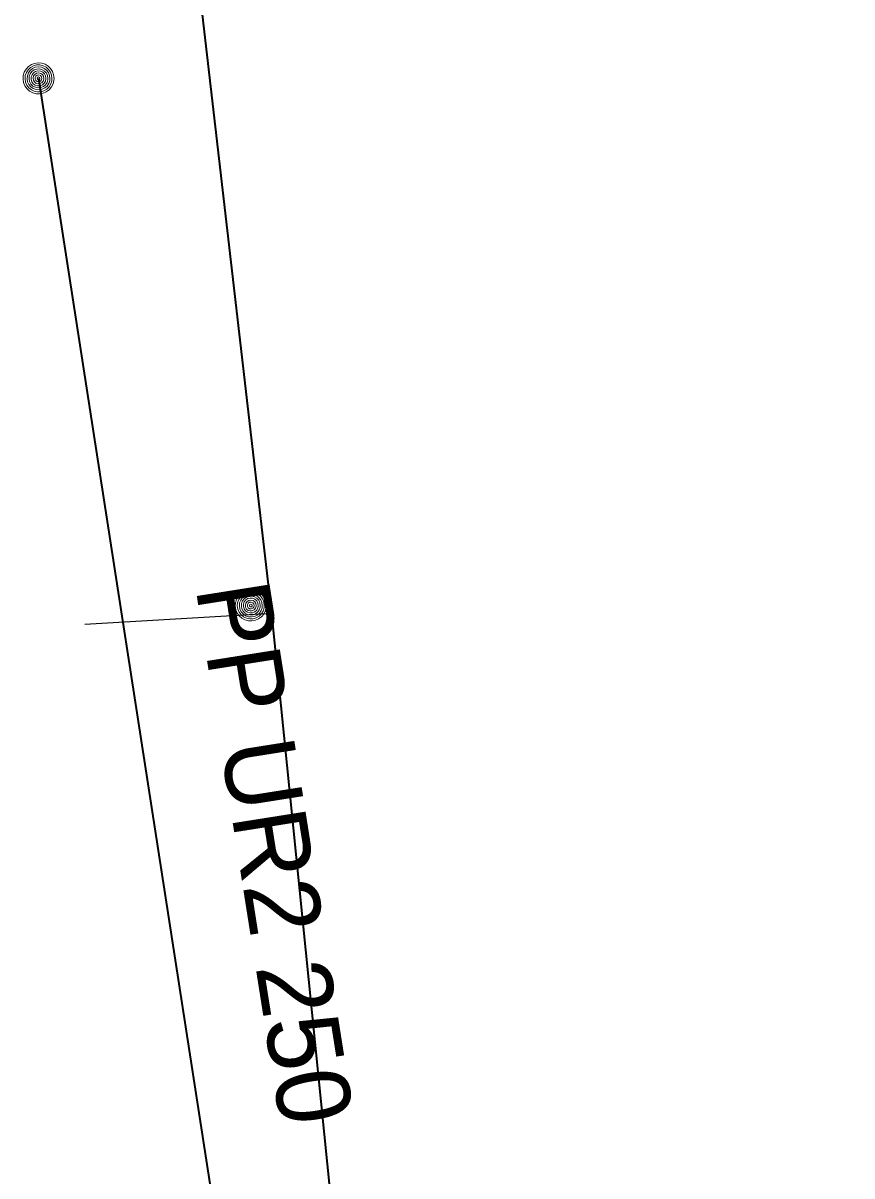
# Model space of a CAD drawing. Extents: x -866761 to -866592, y -1013996 to -1013877.
# Drawn here: x -866633.41 to -866621.04, y -1013918.84 to -1013901.63 of the extents above; entities that cross this region are included whole.
import ezdxf

# ---------------------------------------------------------------- set-up
doc = ezdxf.new("R2010")
doc.units = 0
doc.header["$LTSCALE"] = 0.44
for name, color, linetype, lineweight in [('1', 7, 'Continuous', 35), ('12', 7, 'Continuous', 13), ('21', 7, 'Continuous', 35), ('3', 7, 'Continuous', 25), ('32', 7, 'Continuous', 13)]:
    doc.layers.add(name, color=color, linetype=linetype, lineweight=lineweight)

msp = doc.modelspace()

# ---------------------------------------------------------------- linework, layer by layer
at = {"layer": '1'}
msp.add_lwpolyline([(-866621.036, -1013976.325), (-866622.91, -1013968.373), (-866626.376, -1013941.619), (-866627.386, -1013933.289), (-866629.697, -1013910.45), (-866632.18, -1013888.99), (-866632.46, -1013887.48), (-866632.668, -1013884.429)], dxfattribs=at)
at = {"layer": '12'}
for points in [[(-866629.78, -1013910.329), (-866629.786, -1013910.277), (-866629.803, -1013910.227), (-866629.832, -1013910.183), (-866629.869, -1013910.146), (-866629.914, -1013910.119), (-866629.964, -1013910.102), (-866630.017, -1013910.098), (-866630.069, -1013910.105), (-866630.118, -1013910.124), (-866630.161, -1013910.153), (-866630.197, -1013910.192), (-866630.223, -1013910.237), (-866630.239, -1013910.288), (-866630.242, -1013910.34), (-866630.234, -1013910.392), (-866630.214, -1013910.441), (-866630.183, -1013910.484), (-866630.144, -1013910.518), (-866630.098, -1013910.544), (-866630.047, -1013910.558), (-866629.994, -1013910.56), (-866629.943, -1013910.55), (-866629.895, -1013910.529), (-866629.852, -1013910.498), (-866629.818, -1013910.457), (-866629.794, -1013910.411), (-866629.782, -1013910.36)], [(-866629.81, -1013910.329), (-866629.816, -1013910.28), (-866629.833, -1013910.234), (-866629.861, -1013910.194), (-866629.898, -1013910.162), (-866629.942, -1013910.14), (-866629.99, -1013910.129), (-866630.039, -1013910.129), (-866630.086, -1013910.142), (-866630.129, -1013910.166), (-866630.165, -1013910.199), (-866630.192, -1013910.24), (-866630.208, -1013910.287), (-866630.212, -1013910.336), (-866630.205, -1013910.384), (-866630.186, -1013910.429), (-866630.156, -1013910.469), (-866630.118, -1013910.5), (-866630.074, -1013910.52), (-866630.026, -1013910.53), (-866629.977, -1013910.528), (-866629.93, -1013910.513), (-866629.887, -1013910.488), (-866629.853, -1013910.454), (-866629.827, -1013910.412), (-866629.813, -1013910.365)], [(-866629.84, -1013910.329), (-866629.846, -1013910.284), (-866629.863, -1013910.242), (-866629.891, -1013910.207), (-866629.927, -1013910.18), (-866629.969, -1013910.163), (-866630.014, -1013910.158), (-866630.059, -1013910.164), (-866630.1, -1013910.183), (-866630.135, -1013910.211), (-866630.162, -1013910.248), (-866630.178, -1013910.29), (-866630.182, -1013910.335), (-866630.175, -1013910.38), (-866630.156, -1013910.421), (-866630.127, -1013910.455), (-866630.09, -1013910.481), (-866630.047, -1013910.497), (-866630.002, -1013910.5), (-866629.957, -1013910.492), (-866629.917, -1013910.472), (-866629.883, -1013910.443), (-866629.857, -1013910.405), (-866629.843, -1013910.362)], [(-866629.87, -1013910.329), (-866629.875, -1013910.288), (-866629.893, -1013910.251), (-866629.92, -1013910.22), (-866629.955, -1013910.199), (-866629.995, -1013910.188), (-866630.036, -1013910.19), (-866630.075, -1013910.203), (-866630.109, -1013910.227), (-866630.134, -1013910.259), (-866630.149, -1013910.297), (-866630.152, -1013910.338), (-866630.144, -1013910.378), (-866630.124, -1013910.414), (-866630.095, -1013910.443), (-866630.058, -1013910.462), (-866630.018, -1013910.47), (-866629.977, -1013910.466), (-866629.939, -1013910.451), (-866629.907, -1013910.425), (-866629.884, -1013910.391), (-866629.871, -1013910.352)], [(-866629.9, -1013910.329), (-866629.905, -1013910.293), (-866629.923, -1013910.261), (-866629.949, -1013910.236), (-866629.983, -1013910.221), (-866630.019, -1013910.218), (-866630.054, -1013910.226), (-866630.085, -1013910.246), (-866630.108, -1013910.274), (-866630.121, -1013910.308), (-866630.121, -1013910.345), (-866630.11, -1013910.38), (-866630.089, -1013910.409), (-866630.059, -1013910.43), (-866630.024, -1013910.44), (-866629.987, -1013910.438), (-866629.953, -1013910.424), (-866629.926, -1013910.401), (-866629.907, -1013910.369), (-866629.9, -1013910.334)], [(-866629.93, -1013910.329), (-866629.935, -1013910.298), (-866629.952, -1013910.272), (-866629.978, -1013910.255), (-866630.008, -1013910.248), (-866630.039, -1013910.252), (-866630.066, -1013910.269), (-866630.084, -1013910.293), (-866630.092, -1013910.324), (-866630.088, -1013910.354), (-866630.073, -1013910.382), (-866630.049, -1013910.401), (-866630.019, -1013910.41), (-866629.988, -1013910.407), (-866629.96, -1013910.393), (-866629.94, -1013910.369), (-866629.93, -1013910.34)], [(-866629.96, -1013910.329), (-866629.965, -1013910.305), (-866629.982, -1013910.287), (-866630.005, -1013910.278), (-866630.029, -1013910.281), (-866630.05, -1013910.295), (-866630.061, -1013910.317), (-866630.061, -1013910.342), (-866630.049, -1013910.363), (-866630.029, -1013910.377), (-866630.004, -1013910.38), (-866629.981, -1013910.371), (-866629.965, -1013910.353)], [(-866629.99, -1013910.329), (-866629.995, -1013910.314), (-866630.01, -1013910.308), (-866630.025, -1013910.312), (-866630.032, -1013910.326), (-866630.028, -1013910.341), (-866630.015, -1013910.35), (-866630, -1013910.347), (-866629.99, -1013910.335)]]:
    msp.add_lwpolyline(points, close=True, dxfattribs=at)
at = {"layer": '21'}
msp.add_line((-866633.18, -1013902.46), (-866629.08, -1013928.9), dxfattribs=at)
at = {"layer": '3'}
msp.add_line((-866629.697, -1013910.45), (-866632.49, -1013910.61), dxfattribs=at)
at = {"layer": '32'}
for points in [[(-866632.949, -1013902.46), (-866632.955, -1013902.408), (-866632.972, -1013902.358), (-866633.001, -1013902.314), (-866633.038, -1013902.277), (-866633.083, -1013902.25), (-866633.133, -1013902.233), (-866633.186, -1013902.229), (-866633.238, -1013902.236), (-866633.287, -1013902.255), (-866633.33, -1013902.284), (-866633.366, -1013902.323), (-866633.392, -1013902.368), (-866633.408, -1013902.419), (-866633.411, -1013902.471), (-866633.403, -1013902.523), (-866633.383, -1013902.572), (-866633.352, -1013902.615), (-866633.313, -1013902.649), (-866633.267, -1013902.675), (-866633.216, -1013902.689), (-866633.163, -1013902.691), (-866633.112, -1013902.681), (-866633.064, -1013902.66), (-866633.021, -1013902.629), (-866632.987, -1013902.588), (-866632.963, -1013902.542), (-866632.951, -1013902.491)], [(-866632.979, -1013902.46), (-866632.985, -1013902.411), (-866633.002, -1013902.365), (-866633.03, -1013902.325), (-866633.067, -1013902.293), (-866633.111, -1013902.271), (-866633.159, -1013902.26), (-866633.208, -1013902.26), (-866633.255, -1013902.273), (-866633.298, -1013902.297), (-866633.334, -1013902.33), (-866633.361, -1013902.371), (-866633.377, -1013902.418), (-866633.381, -1013902.467), (-866633.374, -1013902.515), (-866633.355, -1013902.56), (-866633.325, -1013902.6), (-866633.287, -1013902.631), (-866633.243, -1013902.651), (-866633.195, -1013902.661), (-866633.146, -1013902.659), (-866633.099, -1013902.644), (-866633.056, -1013902.619), (-866633.022, -1013902.585), (-866632.996, -1013902.543), (-866632.982, -1013902.496)], [(-866633.009, -1013902.46), (-866633.015, -1013902.415), (-866633.032, -1013902.373), (-866633.06, -1013902.338), (-866633.096, -1013902.311), (-866633.138, -1013902.294), (-866633.183, -1013902.289), (-866633.228, -1013902.295), (-866633.269, -1013902.314), (-866633.304, -1013902.342), (-866633.331, -1013902.379), (-866633.347, -1013902.421), (-866633.351, -1013902.466), (-866633.344, -1013902.511), (-866633.325, -1013902.552), (-866633.296, -1013902.586), (-866633.259, -1013902.612), (-866633.216, -1013902.628), (-866633.171, -1013902.631), (-866633.126, -1013902.623), (-866633.086, -1013902.603), (-866633.052, -1013902.574), (-866633.026, -1013902.536), (-866633.012, -1013902.493)], [(-866633.039, -1013902.46), (-866633.044, -1013902.419), (-866633.062, -1013902.382), (-866633.089, -1013902.351), (-866633.124, -1013902.33), (-866633.164, -1013902.319), (-866633.205, -1013902.321), (-866633.244, -1013902.334), (-866633.278, -1013902.358), (-866633.303, -1013902.39), (-866633.318, -1013902.428), (-866633.321, -1013902.469), (-866633.313, -1013902.509), (-866633.293, -1013902.545), (-866633.264, -1013902.574), (-866633.227, -1013902.593), (-866633.187, -1013902.601), (-866633.146, -1013902.597), (-866633.108, -1013902.582), (-866633.076, -1013902.556), (-866633.053, -1013902.522), (-866633.04, -1013902.483)], [(-866633.069, -1013902.46), (-866633.074, -1013902.424), (-866633.092, -1013902.392), (-866633.118, -1013902.367), (-866633.152, -1013902.352), (-866633.188, -1013902.349), (-866633.223, -1013902.357), (-866633.254, -1013902.377), (-866633.277, -1013902.405), (-866633.29, -1013902.439), (-866633.29, -1013902.476), (-866633.279, -1013902.511), (-866633.258, -1013902.54), (-866633.228, -1013902.561), (-866633.193, -1013902.571), (-866633.156, -1013902.569), (-866633.122, -1013902.555), (-866633.095, -1013902.532), (-866633.076, -1013902.5), (-866633.069, -1013902.465)], [(-866633.099, -1013902.46), (-866633.104, -1013902.429), (-866633.121, -1013902.403), (-866633.147, -1013902.386), (-866633.177, -1013902.379), (-866633.208, -1013902.383), (-866633.235, -1013902.4), (-866633.253, -1013902.424), (-866633.261, -1013902.455), (-866633.257, -1013902.485), (-866633.242, -1013902.513), (-866633.218, -1013902.532), (-866633.188, -1013902.541), (-866633.157, -1013902.538), (-866633.129, -1013902.524), (-866633.109, -1013902.5), (-866633.099, -1013902.471)], [(-866633.129, -1013902.46), (-866633.134, -1013902.436), (-866633.151, -1013902.418), (-866633.174, -1013902.409), (-866633.198, -1013902.412), (-866633.219, -1013902.426), (-866633.23, -1013902.448), (-866633.23, -1013902.473), (-866633.218, -1013902.494), (-866633.198, -1013902.508), (-866633.173, -1013902.511), (-866633.15, -1013902.502), (-866633.134, -1013902.484)], [(-866633.159, -1013902.46), (-866633.164, -1013902.445), (-866633.179, -1013902.439), (-866633.194, -1013902.443), (-866633.201, -1013902.457), (-866633.197, -1013902.472), (-866633.184, -1013902.481), (-866633.169, -1013902.478), (-866633.159, -1013902.466)]]:
    msp.add_lwpolyline(points, close=True, dxfattribs=at)

# ---------------------------------------------------------------- texts
at = {"layer": '1'}
msp.add_text('PP UR2 250', height=1.1, rotation=279, dxfattribs=at).set_placement((-866630.836, -1013910.068))

doc.saveas('drawing.dxf')
